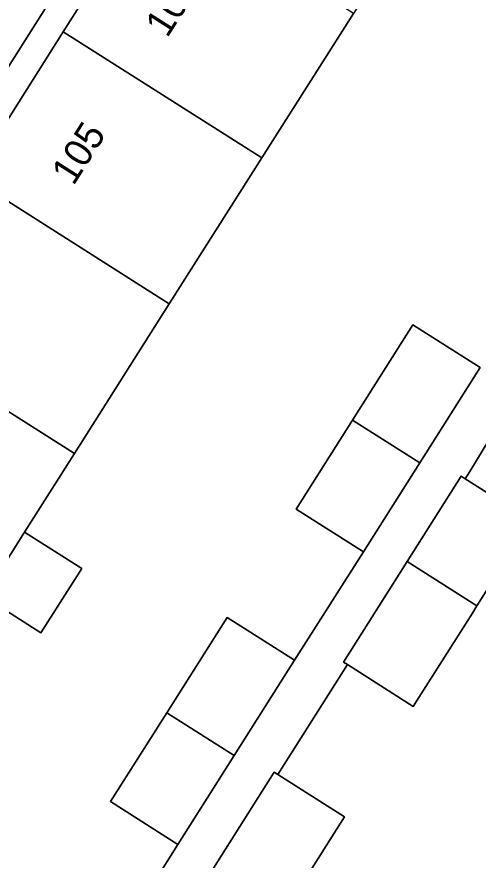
# Model space of a CAD drawing. Extents: x 159039 to 160102, y 381214 to 382524.
# Drawn here: x 159368.79 to 159385.36, y 381818.69 to 381848.96 of the extents above; entities that cross this region are included whole.
import ezdxf

# ---------------------------------------------------------------- set-up
doc = ezdxf.new("R2010")
doc.units = 0
for name, color, linetype in [('IMGEO_Erf', 7, 'Continuous'), ('IMGEO_Pand', 7, 'Continuous'), ('IMGEO_Pand_nummerreeks', 7, 'Continuous'), ('IMGEO_Voetpad_open', 7, 'Continuous')]:
    doc.layers.add(name, color=color, linetype=linetype)

msp = doc.modelspace()

# ---------------------------------------------------------------- linework, layer by layer
at = {"layer": 'IMGEO_Erf'}
for points in [[(159401.551, 381861.756), (159385.148, 381873.477), (159352.77, 381822.367), (159353.599, 381821.842), (159357.08, 381827.327), (159360.473, 381832.674), (159363.729, 381837.804), (159367.14, 381843.178), (159370.464, 381848.417), (159373.755, 381853.601), (159377.079, 381858.84), (159380.405, 381864.08), (159383.895, 381869.579), (159391.026, 381865.053)], [(159387.536, 381859.554), (159384.21, 381854.314), (159380.886, 381849.076), (159377.596, 381843.891), (159374.271, 381838.652), (159370.86, 381833.278), (159369.074, 381830.464), (159371.131, 381829.158), (159369.661, 381826.842), (159367.604, 381828.148), (159365.414, 381824.697), (159367.114, 381823.618), (159365.91, 381821.722), (159364.211, 381822.801), (159360.73, 381817.316)], [(159372.987, 381816.714), (159374.577, 381819.251), (159372.157, 381820.787), (159374.18, 381823.974), (159376.352, 381827.396), (159378.771, 381825.861), (159381.244, 381829.755), (159378.824, 381831.291), (159380.847, 381834.478), (159383.019, 381837.9), (159385.438, 381836.365)], [(159387.39, 381836.462), (159385.062, 381832.633), (159384.902, 381832.38), (159387.268, 381830.878), (159385.322, 381827.812), (159385.156, 381827.55), (159383.238, 381824.527), (159383.033, 381824.205), (159380.666, 381825.707), (159378.163, 381821.763), (159380.564, 381820.24), (159378.44, 381816.892)]]:
    msp.add_lwpolyline(points, dxfattribs=at)
at = {"layer": 'IMGEO_Pand'}
for points in [[(159370.464, 381848.417), (159377.596, 381843.891), (159380.886, 381849.076), (159373.755, 381853.601)], [(159367.14, 381843.178), (159374.271, 381838.652), (159377.596, 381843.891), (159370.464, 381848.417)], [(159367.14, 381843.178), (159363.729, 381837.804), (159370.86, 381833.278), (159374.271, 381838.652)], [(159380.847, 381834.478), (159383.267, 381832.943), (159385.438, 381836.365), (159383.019, 381837.9)], [(159370.86, 381833.278), (159363.729, 381837.804), (159360.473, 381832.674), (159367.604, 381828.148), (159369.074, 381830.464)], [(159380.847, 381834.478), (159378.824, 381831.291), (159381.244, 381829.755), (159383.267, 381832.943)], [(159387.268, 381830.878), (159384.902, 381832.38), (159384.76, 381832.47), (159382.814, 381829.405), (159385.322, 381827.812)], [(159369.074, 381830.464), (159367.604, 381828.148), (159369.661, 381826.842), (159371.131, 381829.158)], [(159385.156, 381827.55), (159385.322, 381827.812), (159382.814, 381829.405), (159380.525, 381825.797), (159380.666, 381825.707), (159383.033, 381824.205), (159383.238, 381824.527)], [(159376.6, 381822.439), (159378.771, 381825.861), (159376.352, 381827.396), (159374.18, 381823.974)], [(159376.6, 381822.439), (159374.18, 381823.974), (159372.157, 381820.787), (159374.577, 381819.251)], [(159378.163, 381821.763), (159378.04, 381821.841), (159375.853, 381818.394), (159378.377, 381816.793), (159378.44, 381816.892), (159380.564, 381820.24)]]:
    msp.add_lwpolyline(points, close=True, dxfattribs=at)
at = {"layer": 'IMGEO_Voetpad_open'}
for points in [[(159315.336, 381791.878), (159316.513, 381793.622), (159318.701, 381796.901), (159323.053, 381803.757), (159328.169, 381811.846), (159329.103, 381813.324), (159339.22, 381829.322), (159340.106, 381828.76), (159347.007, 381824.38), (159352.041, 381821.217), (159352.77, 381822.367), (159385.148, 381873.477)], [(159385.438, 381836.365), (159383.267, 381832.943), (159381.244, 381829.755), (159378.771, 381825.861), (159376.6, 381822.439), (159374.577, 381819.251), (159372.987, 381816.714)], [(159375.853, 381818.394), (159378.04, 381821.841), (159378.163, 381821.763), (159380.666, 381825.707), (159380.525, 381825.797), (159382.814, 381829.405), (159384.76, 381832.47), (159384.902, 381832.38), (159385.062, 381832.633), (159387.39, 381836.462)]]:
    msp.add_lwpolyline(points, dxfattribs=at)

# ---------------------------------------------------------------- texts
at = {"layer": 'IMGEO_Pand_nummerreeks'}
for s, p in [('103', (159374.193, 381848.171)), ('105', (159370.827, 381842.867))]:
    msp.add_text(s, height=1, rotation=57.599, dxfattribs=at).set_placement(p)

doc.saveas('drawing.dxf')
